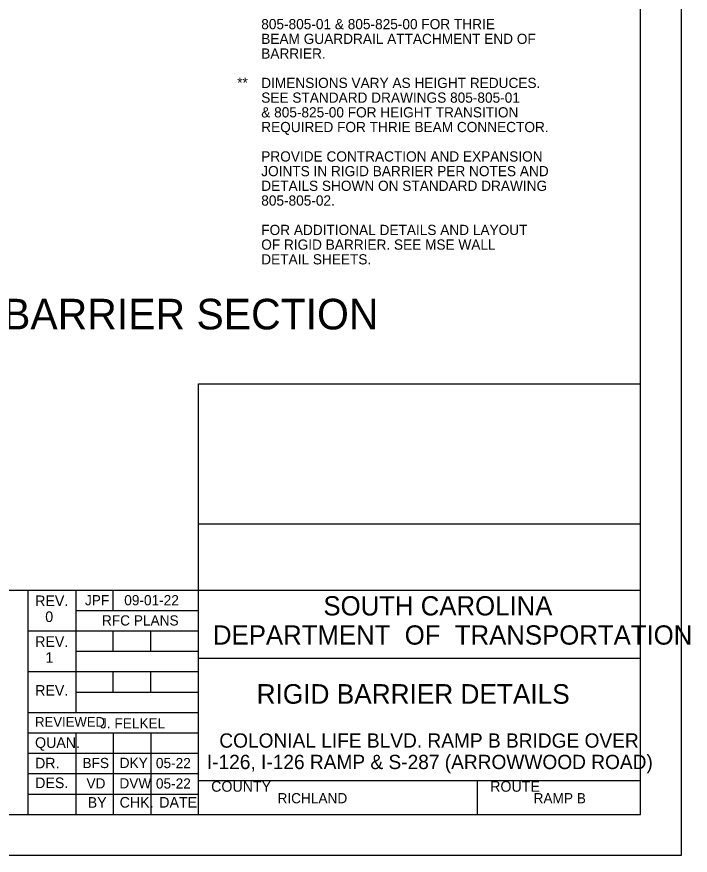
# Model space of a CAD drawing. Extents: x 96 to 240, y 601 to 689.
# Drawn here: x 207.27 to 240.27, y 601 to 642.1 of the extents above; entities that cross this region are included whole.
import ezdxf

# ---------------------------------------------------------------- set-up
doc = ezdxf.new("R2010")
doc.units = 0
for name, color, linetype in [('BR_AUTO DIMENSION', 7, 'Continuous'), ('BR_BORDER LINES', 7, 'Continuous'), ('BR_TEXT', 7, 'Continuous'), ('Level 31', 7, 'Continuous')]:
    doc.layers.add(name, color=color, linetype=linetype)

msp = doc.modelspace()

# ---------------------------------------------------------------- linework, layer by layer
at = {"layer": 'BR_BORDER LINES'}
for p, q in [((237.837, 603.003), (237.837, 687.003)), ((216.17, 603.003), (216.17, 624.11)), ((216.17, 624.11), (237.837, 624.11)), ((216.17, 617.251), (237.837, 617.251)), ((186.375, 614.004), (207.836, 614.004)), ((207.836, 603.003), (207.836, 614.004)), ((207.836, 614.004), (237.837, 614.004)), ((210.169, 614.004), (210.169, 608.004)), ((212.003, 613.004), (212.003, 614.004)), ((210.169, 613.004), (216.17, 613.004)), ((207.836, 612.004), (216.17, 612.004)), ((212.003, 611.004), (212.003, 612.004)), ((213.836, 611.004), (213.836, 612.004)), ((210.169, 611.004), (216.17, 611.004)), ((216.17, 610.67), (216.17, 610.67)), ((216.17, 610.67), (237.838, 610.67)), ((207.836, 610.004), (216.17, 610.004)), ((212.003, 609.004), (212.003, 610.004)), ((213.836, 609.004), (213.836, 610.004)), ((210.169, 609.004), (216.17, 609.004)), ((207.836, 608.004), (216.17, 608.004)), ((207.836, 607.004), (216.17, 607.004)), ((210.169, 607.004), (210.169, 603.003)), ((212.003, 607.004), (212.003, 603.003)), ((213.836, 607.004), (213.836, 603.003)), ((207.836, 606.004), (216.17, 606.004)), ((207.836, 605.004), (216.17, 605.004)), ((216.17, 604.67), (237.837, 604.67)), ((216.56, 604.67), (237.837, 604.67)), ((229.837, 603.003), (229.837, 604.67)), ((207.836, 604.003), (216.17, 604.003)), ((103.173, 603.003), (237.837, 603.003))]:
    msp.add_line(p, q, dxfattribs=at)
at = {"layer": 'Level 31'}
msp.add_line((227.004, 608.909), (227.004, 608.909), dxfattribs=at)
msp.add_lwpolyline([(95.84, 601.004), (239.84, 601.004), (239.84, 689.004), (95.84, 689.004)], close=True, dxfattribs=at)

# ---------------------------------------------------------------- texts
at = {"layer": 'BR_AUTO DIMENSION'}
for s, p in [('805-805-01 & 805-825-00 FOR THRIE', (219.251, 641.491)), ('BEAM GUARDRAIL ATTACHMENT END OF', (219.251, 640.77)), ('BARRIER.', (219.251, 640.05)), ('**', (218.075, 638.62)), ('DIMENSIONS VARY AS HEIGHT REDUCES.', (219.251, 638.609)), ('SEE STANDARD DRAWINGS 805-805-01', (219.251, 637.888)), ('& 805-825-00 FOR HEIGHT TRANSITION', (219.251, 637.168)), ('REQUIRED FOR THRIE BEAM CONNECTOR.', (219.251, 636.447)), ('PROVIDE CONTRACTION AND EXPANSION', (219.251, 635.006)), ('JOINTS IN RIGID BARRIER PER NOTES AND', (219.251, 634.286)), ('DETAILS SHOWN ON STANDARD DRAWING', (219.251, 633.566)), ('805-805-02.', (219.251, 632.845)), ('FOR ADDITIONAL DETAILS AND LAYOUT', (219.251, 631.404)), ('OF RIGID BARRIER. SEE MSE WALL', (219.251, 630.684)), ('DETAIL SHEETS.', (219.251, 629.963))]:
    msp.add_text(s, height=0.5, dxfattribs=at).set_placement(p)
at = {"layer": 'BR_TEXT'}
for s, height, p in [('CONCRETE RIGID BARRIER SECTION', 1.5, (188.661, 626.777)), ('REV.', 0.52, (208.175, 613.216)), ('JPF', 0.5, (210.615, 613.254)), ('09-01-22', 0.5, (212.54, 613.254)), ('SOUTH CAROLINA', 0.94348, (222.297, 612.757)), ('0', 0.52, (208.67, 612.435)), ('RFC PLANS', 0.5, (211.449, 612.263)), ('DEPARTMENT  OF  TRANSPORTATION', 0.94348, (216.886, 611.327)), ('REV.', 0.52, (208.175, 611.215)), ('1', 0.52, (208.678, 610.435)), ('REV.', 0.52, (208.175, 608.825)), ('RIGID BARRIER DETAILS', 0.96, (219.026, 608.429)), ('REVIEWED', 0.48, (208.172, 607.298)), ('J. FELKEL', 0.5, (211.352, 607.221)), ('QUAN.', 0.52, (208.17, 606.264)), ('COLONIAL LIFE BLVD. RAMP B BRIDGE OVER', 0.7, (217.196, 606.276)), ('DR.', 0.52, (208.17, 605.258)), ('05-22', 0.5, (214.091, 605.271)), ('I-126, I-126 RAMP & S-287 (ARROWWOOD ROAD) ', 0.7, (216.587, 605.226)), ('DES.', 0.52, (208.175, 604.293)), ('05-22', 0.5, (214.091, 604.271)), ('COUNTY', 0.52, (216.798, 604.117)), ('ROUTE', 0.52, (230.466, 604.117)), ('BY', 0.52, (210.751, 603.331)), ('CHK.', 0.52, (212.314, 603.337)), ('DATE', 0.52, (214.255, 603.337)), ('RICHLAND', 0.5, (220.047, 603.549)), ('RAMP B', 0.5, (232.591, 603.549))]:
    msp.add_text(s, height=height, dxfattribs=at).set_placement(p)
for s, p in [('BFS', (210.493, 605.275)), ('DKY', (212.317, 605.281)), ('VD', (210.69, 604.275)), ('DVW', (212.303, 604.281))]:
    msp.add_text(s, height=0.5, rotation=360, dxfattribs=at).set_placement(p)

doc.saveas('drawing.dxf')
